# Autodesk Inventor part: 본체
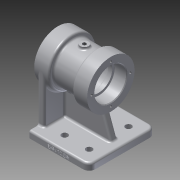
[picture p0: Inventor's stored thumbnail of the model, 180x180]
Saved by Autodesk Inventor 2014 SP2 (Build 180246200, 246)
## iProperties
Created: 2020-06
Part Number: 본체
Material: 알루미늄 6061
Document SubType Name: Modeling
Designer: Administrator
Density: 2.71 g/cm^3
Appearance: 알루미늄 - 평지
Mass: 731.629 g
Surface Area: 645.49 cm^2
Volume: 269.974 cm^3
Author: Administrator
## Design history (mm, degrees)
sketch "스케치1"
  geometry: L1 (-39, 0)-(39, 0); L2 (-39, 23.5)-(-21, 23.5); L3 (-21, 23.5)-(-21, 20); L4 (-21, 20)-(-15, 20); L5 (-15, 20)-(-15, 23); L6 (-15, 23)-(15, 23); L7 (15, 23)-(15, 20); L8 (15, 20)-(21, 20); L9 (21, 20)-(21, 23.5); L10 (21, 23.5)-(39, 23.5); L11 (39, 23.5)-(39, 35); L12 (39, 35)-(17, 35); L13 (17, 35)-(17, 29); L14 (17, 29)-(-17, 29); L15 (-17, 29)-(-17, 35); L16 (-17, 35)-(-39, 35); L17 (-39, 35)-(-39, 23.5); 2 further points
  constraints: 34 end point, 10 parallel, 5 perpendicular, 2 vertical alignment, 1 coincident, 1 collinear, 1 horizontal, 1 midpoint
  dimensions: "d0" = 78 distance of L1.start L1.end; "d1" = 47 diameter of L2 L1; "d2" = 40 diameter of L4 L1; "d3" = 70 diameter of L16 L1; "d4" = 22 distance of L15.end L16.end; "d5" = 22 distance of L11.end L12.end; "d6" = 47 diameter of L10 L1; "d7" = 40 diameter of L8 L1; "d8" = 70 diameter of L12 L1; "d9" = 18 distance of L2.start L2.end; "d10" = 6 distance of L3.end L4.end; "d11" = 30 distance of L5.end L6.end; "d12" = 18 distance of L9.end L10.end; "d13" = 46 diameter of L6 L1; "d14" = 58 diameter of L14 L1
revolve "회전1" sketch "스케치1" stored, may be unused: angle "d15" = 90 deg
node "작업 평면1"
sketch "스케치2"
  geometry: L1 (-34, 49)-(56, 49); L2 (56, 49)-(56, -49); L3 (56, -49)-(-34, -49); L4 (-34, -49)-(-34, 49); L5 (-34, 49)-(36, 49); L6 (36, 49)-(36, 29); L7 (36, 29)-(0, 29); L8 (0, 29)-(0, -29); L9 (0, -29)-(36, -29); L10 (36, -29)-(36, 29); L11 (-39, -35)-(-39, 35) reference; C1 r 4.5 at (36, 29); C2 r 4.5 at (0, 29); C3 r 4.5 at (0, -29); C4 r 4.5 at (36, -29); 2 further points
  constraints: 20 end point, 5 perpendicular, 4 centre point, 4 coincident, 3 parallel, 1 horizontal, 1 horizontal alignment, 1 midpoint, 1 point on line
  dimensions: "d20" = 20 distance of L5.end L6.end; "d21" = 9 diameter of C1; "d22" = 36 distance of L7.start L7.end; "d23" = 58 distance of L7.end L8.end; "d24" = 9 diameter of C2; "d25" = 9 diameter of C3; "d26" = 9 diameter of C4; "d39" = 5 distance between parallel lines of L4 L11; "d40" = 90 distance of L1.start L1.end; "d41" = 70 distance from line of L6.end L4; "d42" = 98 distance of L1.end L2.end
extrude "돌출1" join sketch "스케치2" distance "d27" = 10; taper "d28" = 0 deg
sketch "스케치3"
  geometry: L1 (-34, 49)-(-34, -49) reference; L2 (-34, 0)-(44, 0); L3 (-34, 35)-(-24, 35); L4 (-34, -35)-(-24, -35); L5 (-34, 35)-(-34, -35); L6 (-24, 35)-(-24, -35); 1 further point
  constraints: 10 end point, 1 midpoint, 1 parallel, 1 perpendicular, 1 vertical, 1 vertical alignment
  dimensions: "d31" = 10 distance of L3.start L3.end; "d33" = 10 distance of L4.start L4.end; "d35" = 70 distance of L3.start L4.start
node "작업 평면2"
extrude "돌출2" join sketch "스케치3" stored distance "d51" = 10; taper "d52" = 0 deg
node "작업 평면3"
sketch "스케치5"
  geometry: L1 (-39, -22.962)-(-21, -22.962) reference; L2 (-21, -22.962)-(-21, -19.365) reference; L3 (-21, -19.365)-(-15, -19.365) reference; L4 (-15, -19.365)-(-15, -22.45) reference; L5 (-15, -22.45)-(15, -22.45) reference; L6 (15, -22.45)-(15, -19.365) reference; L7 (15, -19.365)-(21, -19.365) reference; L8 (21, -19.365)-(21, -22.962) reference; L9 (21, -22.962)-(39, -22.962) reference; L10 (39, -22.962)-(39, -34.641) reference; L11 (39, -34.641)-(17, -34.641) reference; L12 (17, -34.641)-(17, -28.566) reference; L13 (17, -28.566)-(-17, -28.566) reference; L14 (-17, -28.566)-(-17, -34.641) reference; L15 (-17, -34.641)-(-24, -34.641) reference; L16 (-24, -34.641)-(-24, -70) reference; L17 (-24, -70)-(56, -70) reference; L18 (56, -70)-(56, -80) reference; L19 (56, -80)-(-34, -80) reference; L20 (-34, -80)-(-34, -34.641) reference; L21 (-34, -34.641)-(-39, -34.641) reference; L22 (-39, -34.641)-(-39, -22.962) reference; L23 (-21, 22.962)-(-39, 22.962) reference; L24 (-39, 22.962)-(-39, 34.641) reference; L25 (-39, 34.641)-(-17, 34.641) reference; L26 (-17, 34.641)-(-17, 28.566) reference; L27 (-17, 28.566)-(17, 28.566) reference; L28 (17, 28.566)-(17, 34.641) reference; L29 (17, 34.641)-(39, 34.641) reference; L30 (39, 34.641)-(39, 22.962) reference; L31 (39, 22.962)-(21, 22.962) reference; L32 (21, 22.962)-(21, 19.365) reference; L33 (21, 19.365)-(15, 19.365) reference; L34 (15, 19.365)-(15, 22.45) reference; L35 (15, 22.45)-(-15, 22.45) reference; L36 (-15, 22.45)-(-15, 19.365) reference; L37 (-15, 19.365)-(-21, 19.365) reference; L38 (-21, 19.365)-(-21, 22.962) reference; L39 (56, -70)-(44, -70); L40 (44, -70)-(31.13, -34.641); L41 (31.13, -34.641)-(17, -34.641); L42 (17, -28.566)-(-17, -28.566); L43 (-17, -34.641)-(-24, -34.641); L44 (-24, -70)-(-24, -34.641); L45 (-17, -34.641)-(-17, -28.566); L46 (17, -28.566)-(17, -34.641); L47 (-24, -70)-(44, -70); 1 further point
  constraints: 18 end point, 6 collinear, 2 point on line, 1 parallel
  dimensions: "d54" = 12 distance of L17.end L39.end; "d55" = 110 deg angle of L39 L40
extrude "돌출3" join sketch "스케치5" distance "d56" = 10; taper "d57" = 0 deg
node "작업 평면4"
sketch "스케치7" dims "d61" = 57
  geometry: L1 (0, 0)-(0, 28.5); C1 r 23.5 at (0, 0) reference
  constraints: 2 end point, 1 coincident, 1 vertical, 1 vertical alignment, 2 other
hole "구멍1" sketch "스케치7" at (0, 28.5) diameter "d62" = 3.242; stored, may be unused: countersink angle "d66" = 90 deg, drill point angle "d68" = 118 deg; dims "d63" = 10, "d64" = 4, "d65" = 2, "d67" = 12
fillet "모깎기1" dims "d79" = 3
chamfer "모따기1" distance "d80" = 1; stored, may be unused: second distance "d81" = 2, angle "d82" = 45 deg
fillet "모깎기2" dims "d83" = 3, "d84" = 0.3
sketch "스케치11"
  geometry: L1 (0, 0)-(0, 7) reference; L2 (0, 0)-(90, 0) reference; 2 further points
  constraints: 1 other
  dimensions: "d93" = 45 distance from line of point (45, 4) L1; "d94" = 4 distance from line of L2 point (45, 4)
feature "엠보싱1" sketch "스케치11" dims "d95" = 0.5, "d96" = 0
node "작업 평면6"
sketch "스케치12"
  geometry: C1 r 6 at (0, 0); 1 further point
  constraints: 1 centre point, 1 coincident
  dimensions: "d98" = 12 diameter of C1
extrude "돌출5" join sketch "스케치12" stored distance "d99" = 3; taper "d100" = 0 deg
fillet "모깎기3" dims "d101" = 3
sketch "스케치13"
  geometry: A1 r 6 centre (0, 0) between (6, 0) and (-6, 0) reference
hole "구멍4" sketch "스케치13" at (0, 0) diameter "d102" = 5.188; stored, may be unused: countersink angle "d106" = 90 deg, drill point angle "d108" = 0 deg; dims "d103" = 10, "d104" = 4, "d105" = 2, "d107" = 12
fillet "모깎기4" dims "d109" = 9
fillet "모깎기5" dims "d110" = 3
fillet "모깎기6" dims "d111" = 3
fillet "모깎기7" dims "d112" = 3
fillet "모깎기8" dims "d113" = 3
fillet "모깎기9" dims "d114" = 3
node "솔리드1"
pattern_circular "원형 패턴1" dims angle "d70" = 360 deg
mirror "대칭1"
node "절단 모서리 투영1"
other parameters: "d44" = 5, "d53" = 5, "d97" = 32
